// SIMATIC S7-200 SMART project (STEP 7-Micro/WIN SMART), CPU ST20

SYMBOL_TABLE BD4523
Pointer          VD2572   // BD4523参数开始地址
StateMachine     VB2576   // 状态机
ErrorCode        VB2577   // 错误码
Pointer1         VD2578
Pointer2         VD2582
Pointer3         VD2586
Timer1           VW2590
STAT             VB2592
CTRB1            VB2594   // 控制字节1
Ctr0             V2594.0
Ctr1             V2594.1
Ctr2             V2594.2
Ctr3             V2594.3
Ctr4             V2594.4
Ctr5             V2594.5
Ctr6             V2594.6
Ctr7             V2594.7
CTRB2            VB2595   // 控制字节2
Ctr8             V2595.0
Ctr9             V2595.1
Ctr10            V2595.2
Ctr11            V2595.3
Ctr12            V2595.4
Ctr13            V2595.5
Ctr14            V2595.6
Ctr15            V2595.7
ADRR             VD2596   // 整定通信占用
TUNE             VW2600   // 整定通信占用
Pointer4         VD2602
Pointer5         VD2606
PtrOUTc          VD2610
PtrOUTa          VD2614
END_SYMBOL_TABLE

SYMBOL_TABLE 用户定义1
间隔               VB2211
从站计数             VB2212
MBusOK           M10.0
Start            M10.1
Done             M10.2
模块站号             VB2213
参数首地址            VD2214
错误码              VB2218
END_SYMBOL_TABLE

ORGANIZATION_BLOCK 主程序:OB1
TITLE=程序注释
BEGIN
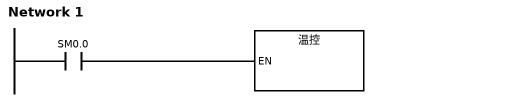
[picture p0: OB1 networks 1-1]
Network 1
LD     SM0.0
CALL   温控:SBR0
END_ORGANIZATION_BLOCK

SUBROUTINE_BLOCK 温控:SBR0
TITLE=子程序注释
BEGIN
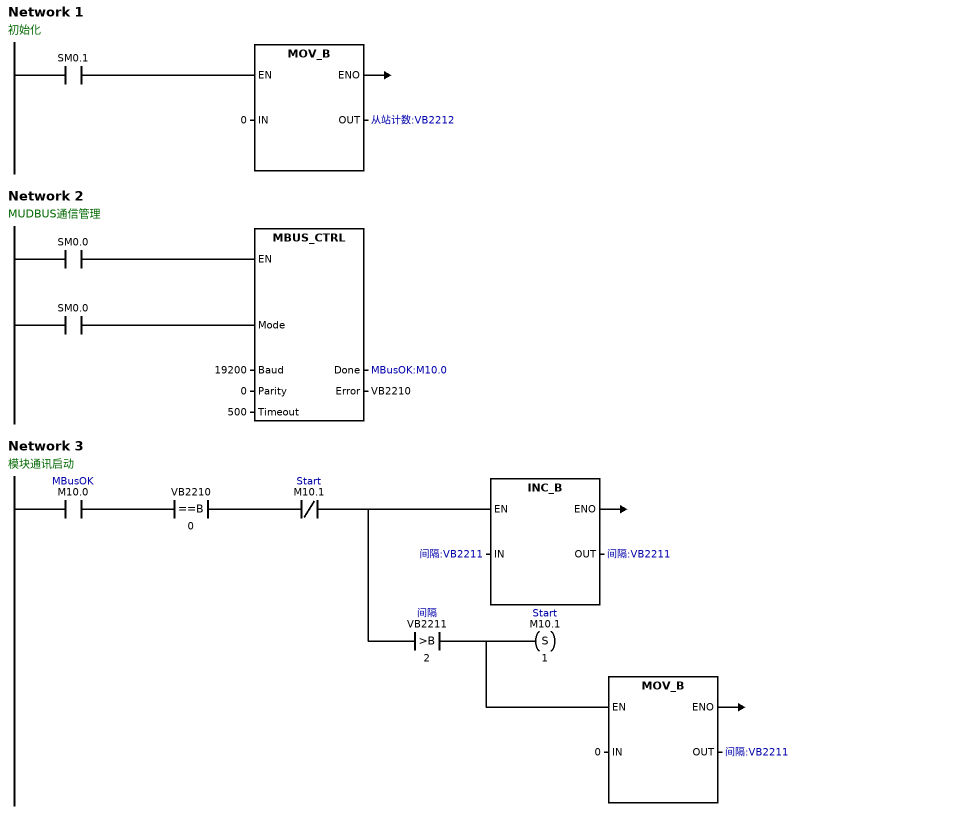
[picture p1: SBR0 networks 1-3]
Network 1
// 初始化
LD     SM0.1
MOVB   0, 从站计数:VB2212
Network 2
// MUDBUS通信管理
LD     SM0.0
=      L60.0
LD     SM0.0
=      L63.7
LD     L60.0
CALL   MBUS_CTRL:SBR1, L63.7, 19200, 0, 500, MBusOK:M10.0, VB2210
Network 3
// 模块通讯启动
LD     MBusOK:M10.0
AB=    VB2210, 0
AN     Start:M10.1
INCB   间隔:VB2211
AB>    间隔:VB2211, 2
S      Start:M10.1, 1
MOVB   0, 间隔:VB2211
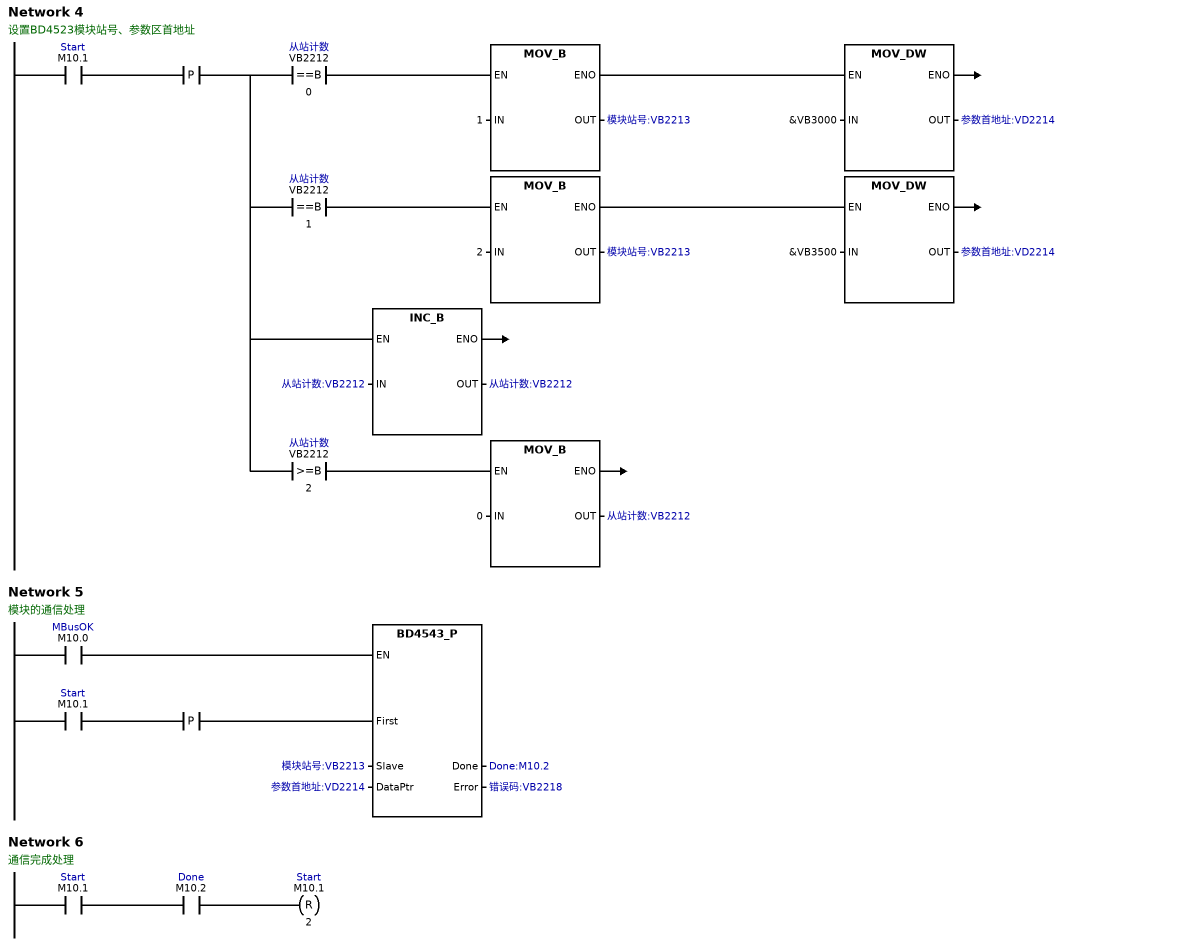
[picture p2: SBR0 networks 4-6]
Network 4
// 设置BD4523模块站号、参数区首地址
// (network saved uncompiled; LAD cells follow)
// row 0: c0 -| |- Start:M10.1  c1 -|P|-  v  c2 -|==B|- 从站计数:VB2212, 0  c3 --  c4 [MOV_B EN:=power@row0, IN:=1, ENO=>power, OUT=>模块站号:VB2213]  c5 --  c6 --  c7 [MOV_DW EN:=power@row0, IN:=&VB3000, ENO=>power, OUT=>参数首地址:VD2214]  c8 ->
// row 1: c1 ^v  c4 [box]  c7 [box]
// row 2: c1 ^v  c2 -|==B|- 从站计数:VB2212, 1  c3 --  c4 [MOV_B EN:=power@row2, IN:=2, ENO=>power, OUT=>模块站号:VB2213]  c5 --  c6 --  c7 [MOV_DW EN:=power@row2, IN:=&VB3500, ENO=>power, OUT=>参数首地址:VD2214]  c8 ->
// row 3: c1 ^v  c4 [box]  c7 [box]
// row 4: c1 ^v  c2 --  c3 [INC_B EN:=power@row4, IN:=从站计数:VB2212, ENO=>power, OUT=>从站计数:VB2212]  c4 ->
// row 5: c1 ^v  c3 [box]
// row 6: c1 ^  c2 -|>=B|- 从站计数:VB2212, 2  c3 --  c4 [MOV_B EN:=power@row6, IN:=0, ENO=>power, OUT=>从站计数:VB2212]  c5 ->
// row 7: c4 [box]
Network 5
// 模块的通信处理
LD     MBusOK:M10.0
=      L60.0
LD     Start:M10.1
EU
=      L63.7
LD     L60.0
CALL   BD4543_P:SBR4, L63.7, 模块站号:VB2213, 参数首地址:VD2214, Done:M10.2, 错误码:VB2218
Network 6
// 通信完成处理
LD     Start:M10.1
A      Done:M10.2
R      Start:M10.1, 2
END_SUBROUTINE_BLOCK

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
SUBROUTINE_BLOCK BD4543_P:SBR4
TITLE=
VAR_INPUT
First:BOOL;	// L0.0 仅需扫描1次
Slave:BYTE;	// LB1 模块站号
DataPtr:DWORD;	// LD2 数据存储区首地址（指针）
END_VAR
VAR_OUTPUT
Done:BOOL;	// L6.0 完成标记。（=0 忙、=1 完成）
Error:BYTE;	// LB7 错误码。（=0 无错误，其余值参考MBUS_MSG）
END_VAR
VAR
DONE1:BOOL;	// L8.0 
DONE2:BOOL;	// L8.1 
DONE3:BOOL;	// L8.2 
DONE4:BOOL;	// L8.3 
DONE5:BOOL;	// L8.4 
Difference1:BOOL;	// L8.5 
Difference2:BOOL;	// L8.6 
MR:BOOL;	// L8.7 
LBT0:BOOL;	// L9.0 
LBT1:BOOL;	// L9.1 
LBT2:BOOL;	// L9.2 
LBT3:BOOL;	// L9.3 
Buff_col:BOOL;	// L9.4 
ERR2:BYTE;	// LB10 
ERR3:BYTE;	// LB11 
ERR4:BYTE;	// LB12 
ERR5:BYTE;	// LB13 
Ptr:DWORD;	// LD14 
Channel:INT;	// LW18 
PointerA:DWORD;	// LD20 
PointerB:DWORD;	// LD24 
Ptr1:DWORD;	// LD28 
PtrOUTa:DWORD;	// LD32 
PtrOUTc:DWORD;	// LD36 
TEM:INT;	// LW40 
counter:BYTE;	// LB42 
PointerC:DWORD;	// LD43 
ERR1:BYTE;	// LB47 
CHX:BYTE;	// LB48 
Buff_b:BYTE;	// LB49 
END_VAR
BEGIN
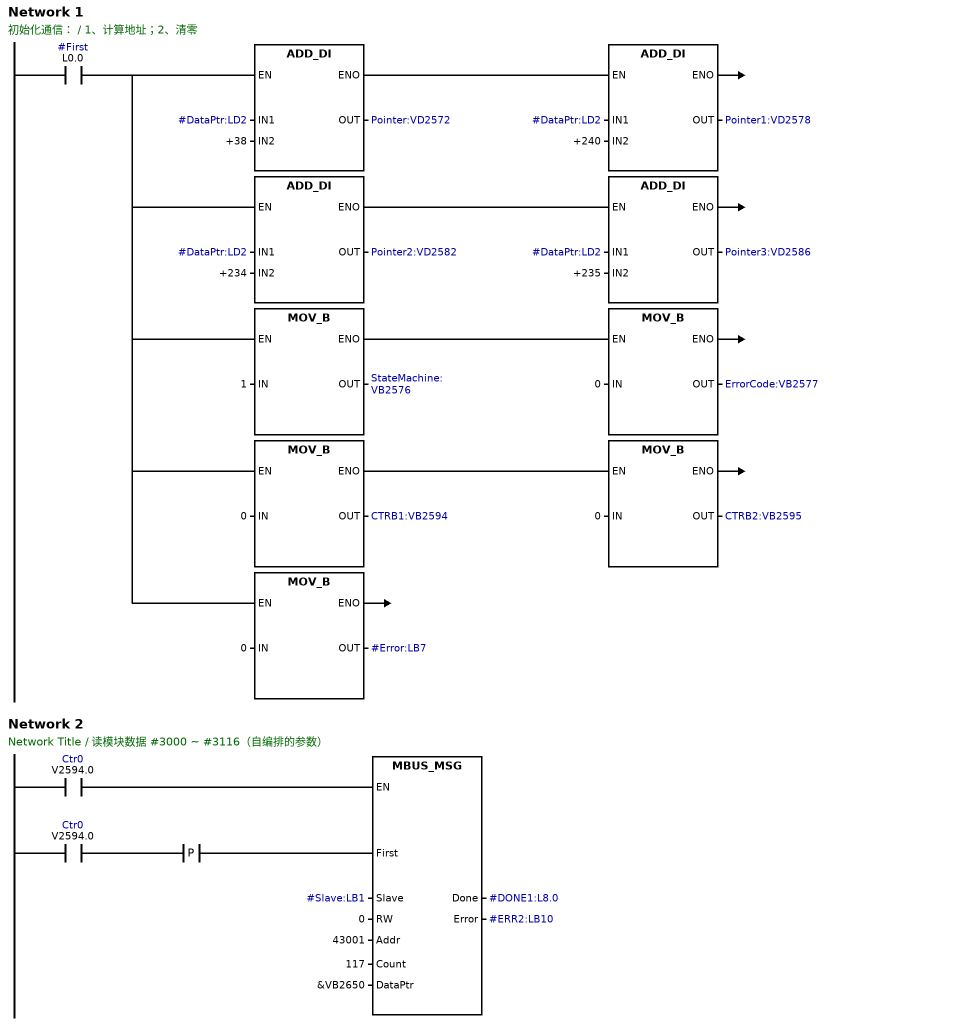
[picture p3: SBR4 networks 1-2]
Network 1
// 初始化通信：
// 1、计算地址；2、清零
LD     #First:L0.0
LPS
MOVD   #DataPtr:LD2, Pointer:VD2572
AENO
+D     +38, Pointer:VD2572
AENO
MOVD   #DataPtr:LD2, Pointer1:VD2578
+D     +240, Pointer1:VD2578
LRD
MOVD   #DataPtr:LD2, Pointer2:VD2582
AENO
+D     +234, Pointer2:VD2582
AENO
MOVD   #DataPtr:LD2, Pointer3:VD2586
+D     +235, Pointer3:VD2586
LRD
MOVB   1, StateMachine:VB2576
AENO
MOVB   0, ErrorCode:VB2577
LRD
MOVB   0, CTRB1:VB2594
AENO
MOVB   0, CTRB2:VB2595
LPP
MOVB   0, #Error:LB7
Network 2
// Network Title
// 读模块数据 #3000 ~ #3116（自编排的参数）
LD     Ctr0:V2594.0
=      L60.0
LD     Ctr0:V2594.0
EU
=      L63.7
LD     L60.0
CALL   MBUS_MSG:SBR2, L63.7, #Slave:LB1, 0, 43001, 117, &VB2650, #DONE1:L8.0, #ERR2:LB10
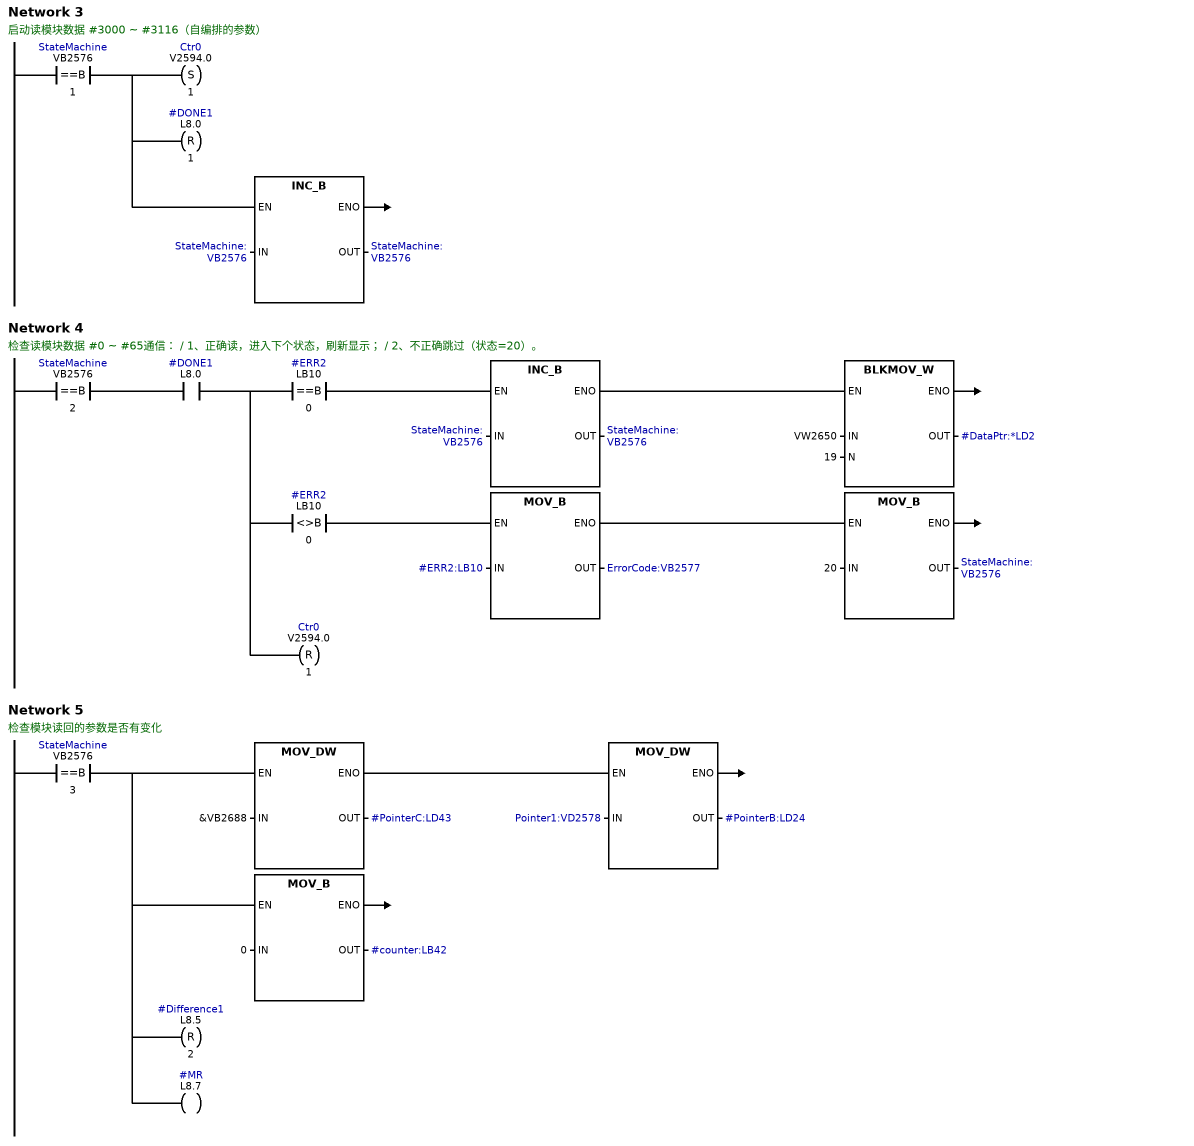
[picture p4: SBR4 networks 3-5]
Network 3
// 启动读模块数据 #3000 ~ #3116（自编排的参数）
LDB=   StateMachine:VB2576, 1
S      Ctr0:V2594.0, 1
R      #DONE1:L8.0, 1
INCB   StateMachine:VB2576
Network 4
// 检查读模块数据 #0 ~ #65通信：
// 1、正确读，进入下个状态，刷新显示；
// 2、不正确跳过（状态=20）。
LDB=   StateMachine:VB2576, 2
A      #DONE1:L8.0
LPS
AB=    #ERR2:LB10, 0
INCB   StateMachine:VB2576
AENO
BMW    VW2650, *#DataPtr:LD2, 19
LRD
AB<>   #ERR2:LB10, 0
MOVB   #ERR2:LB10, ErrorCode:VB2577
AENO
MOVB   20, StateMachine:VB2576
LPP
R      Ctr0:V2594.0, 1
Network 5
// 检查模块读回的参数是否有变化
LDB=   StateMachine:VB2576, 3
LPS
MOVD   &VB2688, #PointerC:LD43
AENO
MOVD   Pointer1:VD2578, #PointerB:LD24
LRD
MOVB   0, #counter:LB42
LRD
R      #Difference1:L8.5, 2
LPP
=      #MR:L8.7
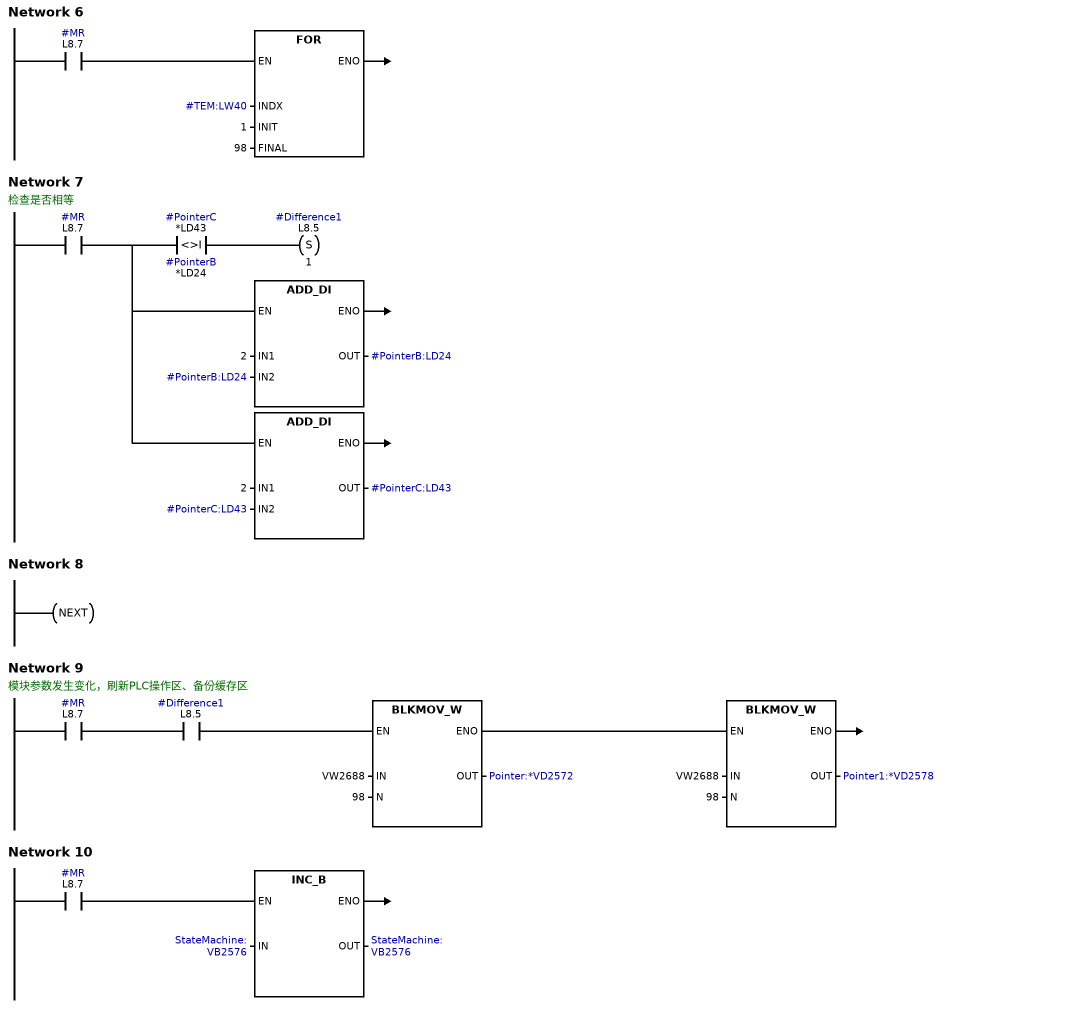
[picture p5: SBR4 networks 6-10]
Network 6
LD     #MR:L8.7
FOR    #TEM:LW40, 1, 98
Network 7
// 检查是否相等
LD     #MR:L8.7
LPS
AW<>   *#PointerC:LD43, *#PointerB:LD24
S      #Difference1:L8.5, 1
LRD
+D     2, #PointerB:LD24
LPP
+D     2, #PointerC:LD43
Network 8
NEXT
Network 9
// 模块参数发生变化，刷新PLC操作区、备份缓存区
LD     #MR:L8.7
A      #Difference1:L8.5
BMW    VW2688, *Pointer:VD2572, 98
AENO
BMW    VW2688, *Pointer1:VD2578, 98
Network 10
LD     #MR:L8.7
INCB   StateMachine:VB2576
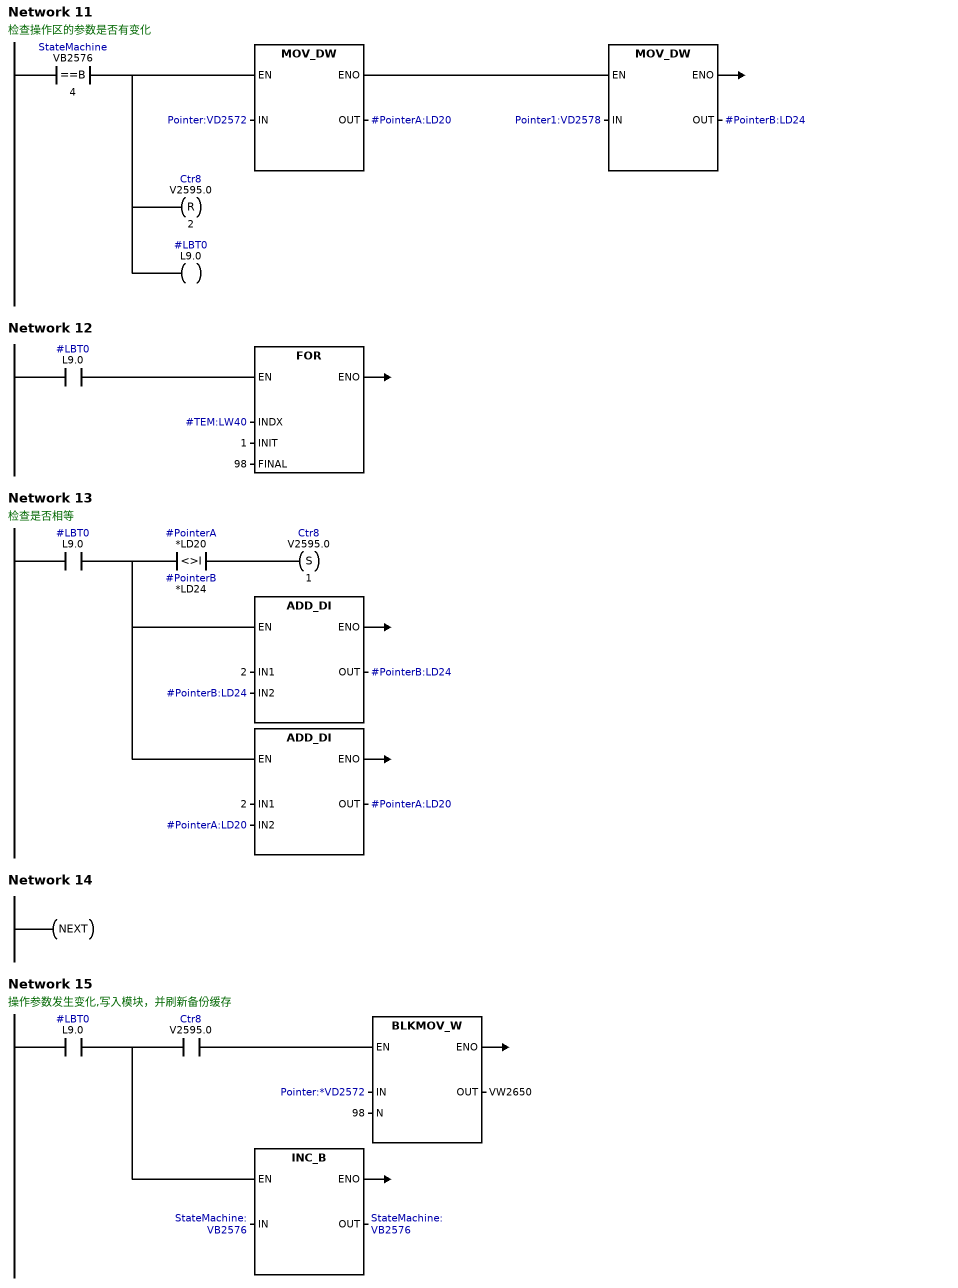
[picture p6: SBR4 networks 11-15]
Network 11
// 检查操作区的参数是否有变化
LDB=   StateMachine:VB2576, 4
LPS
MOVD   Pointer:VD2572, #PointerA:LD20
AENO
MOVD   Pointer1:VD2578, #PointerB:LD24
LRD
R      Ctr8:V2595.0, 2
LPP
=      #LBT0:L9.0
Network 12
LD     #LBT0:L9.0
FOR    #TEM:LW40, 1, 98
Network 13
// 检查是否相等
LD     #LBT0:L9.0
LPS
AW<>   *#PointerA:LD20, *#PointerB:LD24
S      Ctr8:V2595.0, 1
LRD
+D     2, #PointerB:LD24
LPP
+D     2, #PointerA:LD20
Network 14
NEXT
Network 15
// 操作参数发生变化,写入模块，并刷新备份缓存
LD     #LBT0:L9.0
LPS
A      Ctr8:V2595.0
BMW    *Pointer:VD2572, VW2650, 98
LPP
INCB   StateMachine:VB2576
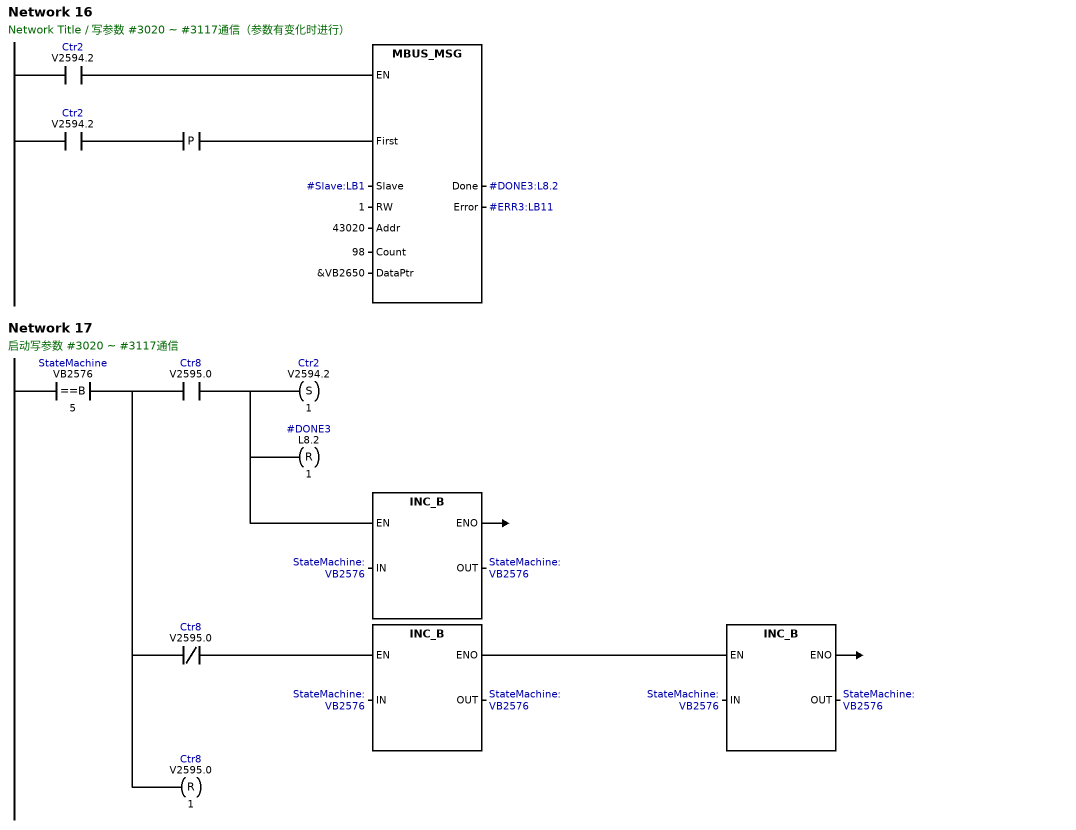
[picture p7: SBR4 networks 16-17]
Network 16
// Network Title
// 写参数 #3020 ~ #3117通信（参数有变化时进行）
LD     Ctr2:V2594.2
=      L60.0
LD     Ctr2:V2594.2
EU
=      L63.7
LD     L60.0
CALL   MBUS_MSG:SBR2, L63.7, #Slave:LB1, 1, 43020, 98, &VB2650, #DONE3:L8.2, #ERR3:LB11
Network 17
// 启动写参数 #3020 ~ #3117通信
LDB=   StateMachine:VB2576, 5
LPS
A      Ctr8:V2595.0
S      Ctr2:V2594.2, 1
R      #DONE3:L8.2, 1
INCB   StateMachine:VB2576
LPP
LPS
AN     Ctr8:V2595.0
INCB   StateMachine:VB2576
AENO
INCB   StateMachine:VB2576
LPP
R      Ctr8:V2595.0, 1
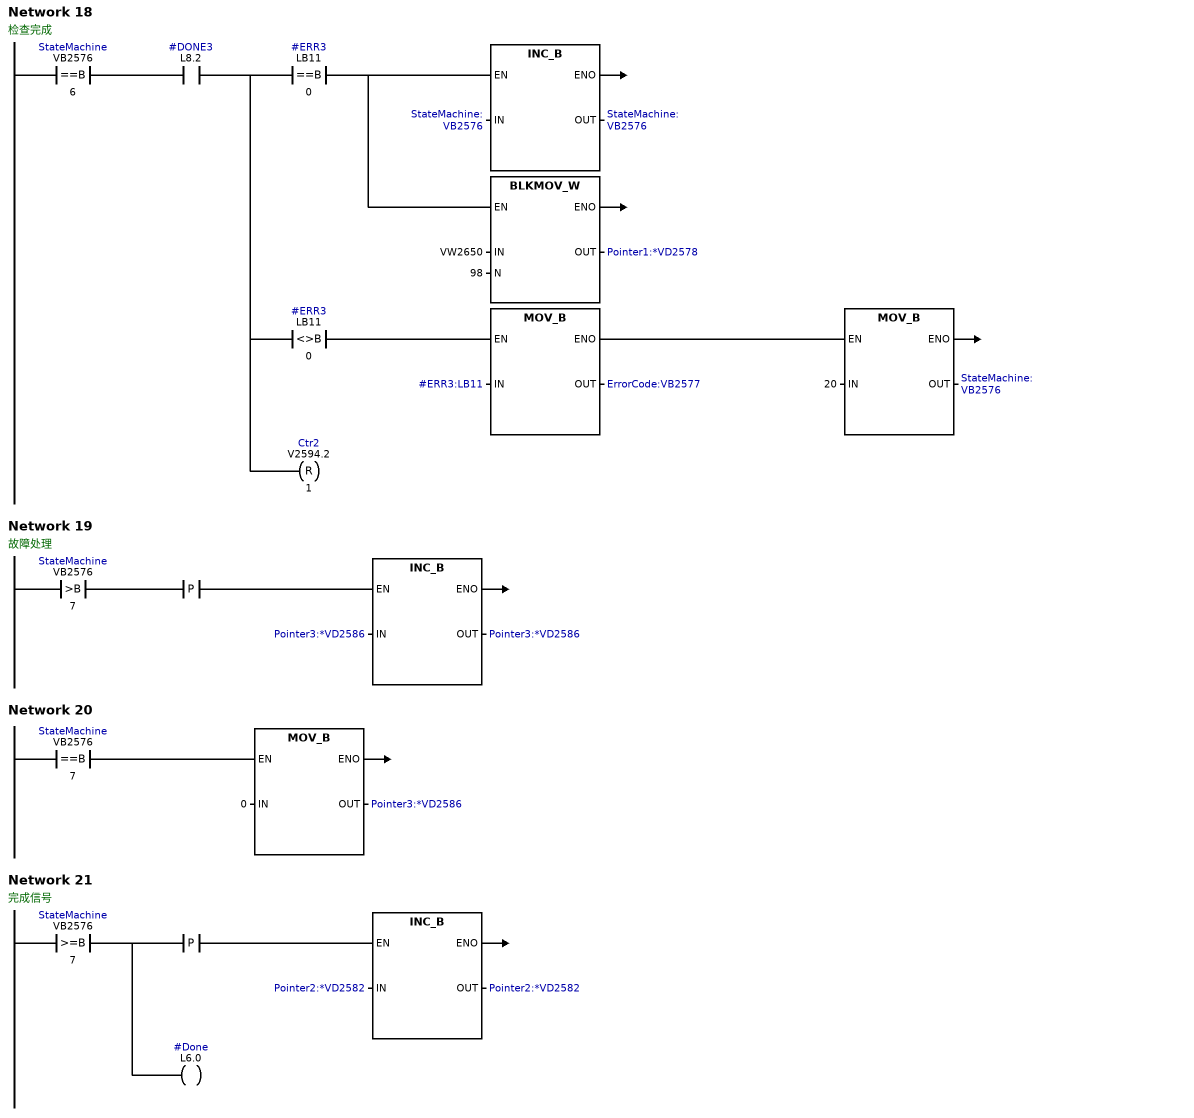
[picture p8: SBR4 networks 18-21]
Network 18
// 检查完成
LDB=   StateMachine:VB2576, 6
A      #DONE3:L8.2
LPS
AB=    #ERR3:LB11, 0
INCB   StateMachine:VB2576
BMW    VW2650, *Pointer1:VD2578, 98
LPP
LPS
AB<>   #ERR3:LB11, 0
MOVB   #ERR3:LB11, ErrorCode:VB2577
AENO
MOVB   20, StateMachine:VB2576
LPP
R      Ctr2:V2594.2, 1
Network 19
// 故障处理
LDB>   StateMachine:VB2576, 7
EU
INCB   *Pointer3:VD2586
Network 20
LDB=   StateMachine:VB2576, 7
MOVB   0, *Pointer3:VD2586
Network 21
// 完成信号
LDB>=  StateMachine:VB2576, 7
LPS
EU
INCB   *Pointer2:VD2582
LPP
=      #Done:L6.0
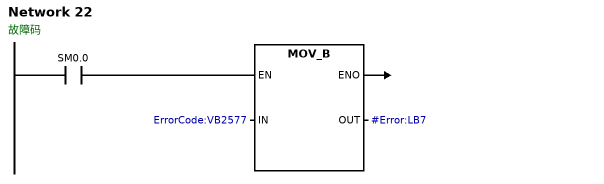
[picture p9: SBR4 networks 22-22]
Network 22
// 故障码
LD     SM0.0
MOVB   ErrorCode:VB2577, #Error:LB7
END_SUBROUTINE_BLOCK
